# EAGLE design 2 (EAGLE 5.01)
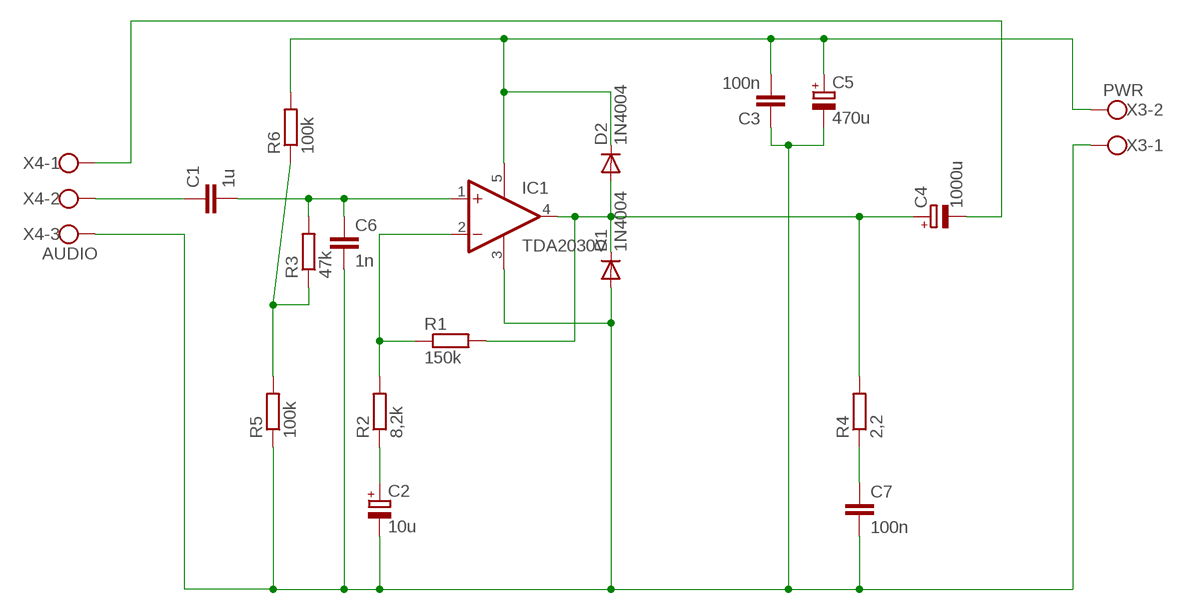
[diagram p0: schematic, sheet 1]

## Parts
C1  1u  C-EU075-042X103  [C075-042X103]
C2  10u  CPOL-EUE2.5-5  [E2,5-5]
C3  100n  C-EU075-032X103  [C075-032X103]
C4  1000u  CPOL-EUE5-10.5  [E5-10,5]
C5  470u  CPOL-EUE5-8.5  [E5-8,5]
C6  1n  C-EU050-025X075  [C050-025X075]
C7  100n  C-EU075-032X103  [C075-032X103]
D1  1N4004  [DO41-10]
D2  1N4004  [DO41-10]
IC1  TDA2030V  [CB360]
R1  150k  R-EU_0207/12  [0207/12]
R2  8,2k  R-EU_0207/12  [0207/12]
R3  47k  R-EU_0207/12  [0207/12]
R4  2,2  R-EU_0207/12  [0207/12]
R5  100k  R-EU_0207/12  [0207/12]
R6  100k  R-EU_0207/12  [0207/12]
X3  PWR  W237-102  [W237-102]
X4  AUDIO  W237-3E  [W237-3E]

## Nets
GND: C2.- C3.1 C5.- C6.2 C7.2 D1.A IC1.3(GND) R5.1 X3.1 X4.3
N$1: C4.- X4.1
N$2: R3.1 R5.2 R6.1
N$5: IC1.2(-IN) R1.1 R2.2
N$6: C2.+ R2.1
N$8: C4.+ D1.C D2.A IC1.4(OUT) R1.2 R4.2
N$9: C7.1 R4.1
N$11: C1.1 X4.2
SIGNAL: C1.2 C6.1 IC1.1(+IN) R3.2
VCC: C3.2 C5.+ D2.C IC1.5(V+) R6.2 X3.2

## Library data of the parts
C1 C3 C6 C7 = rcl:C-EU: CAPACITOR, European symbol
C2 C4 C5 = rcl:CPOL-EU: POLARIZED CAPACITOR, European symbol
D1 D2 = diode:1N4004: DIODE
IC1 = linear:TDA2030: Power OP AMP
R1-R6 = rcl:R-EU_: RESISTOR, European symbol
X3 = con-wago-500:W237-102: WAGO SCREW CLAMP
X4 = con-wago-508:W237-3E: WAGO SREW CLAMP

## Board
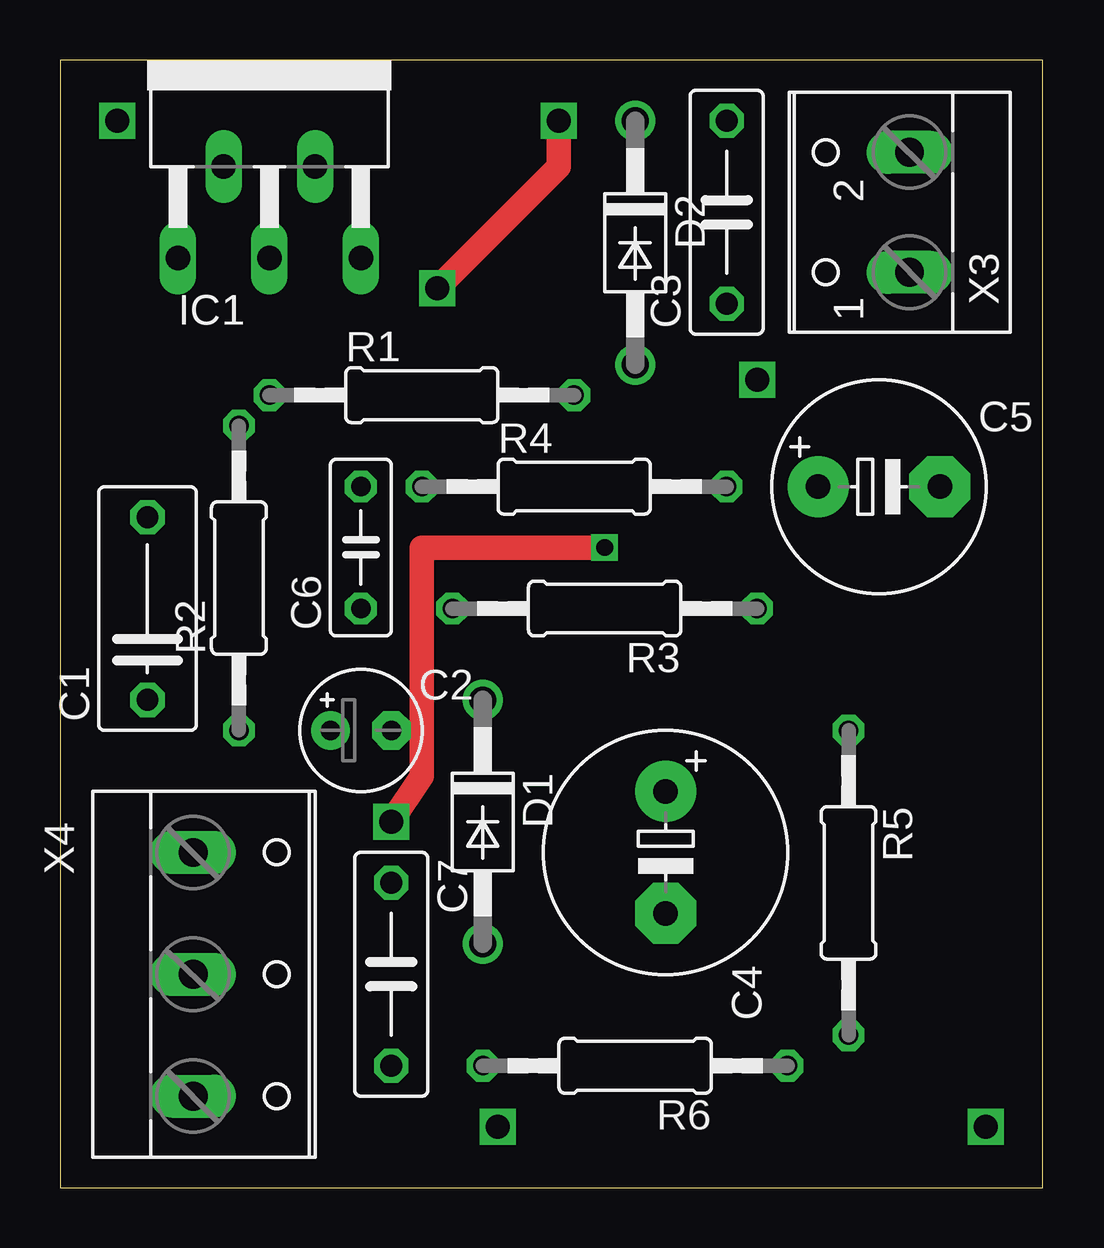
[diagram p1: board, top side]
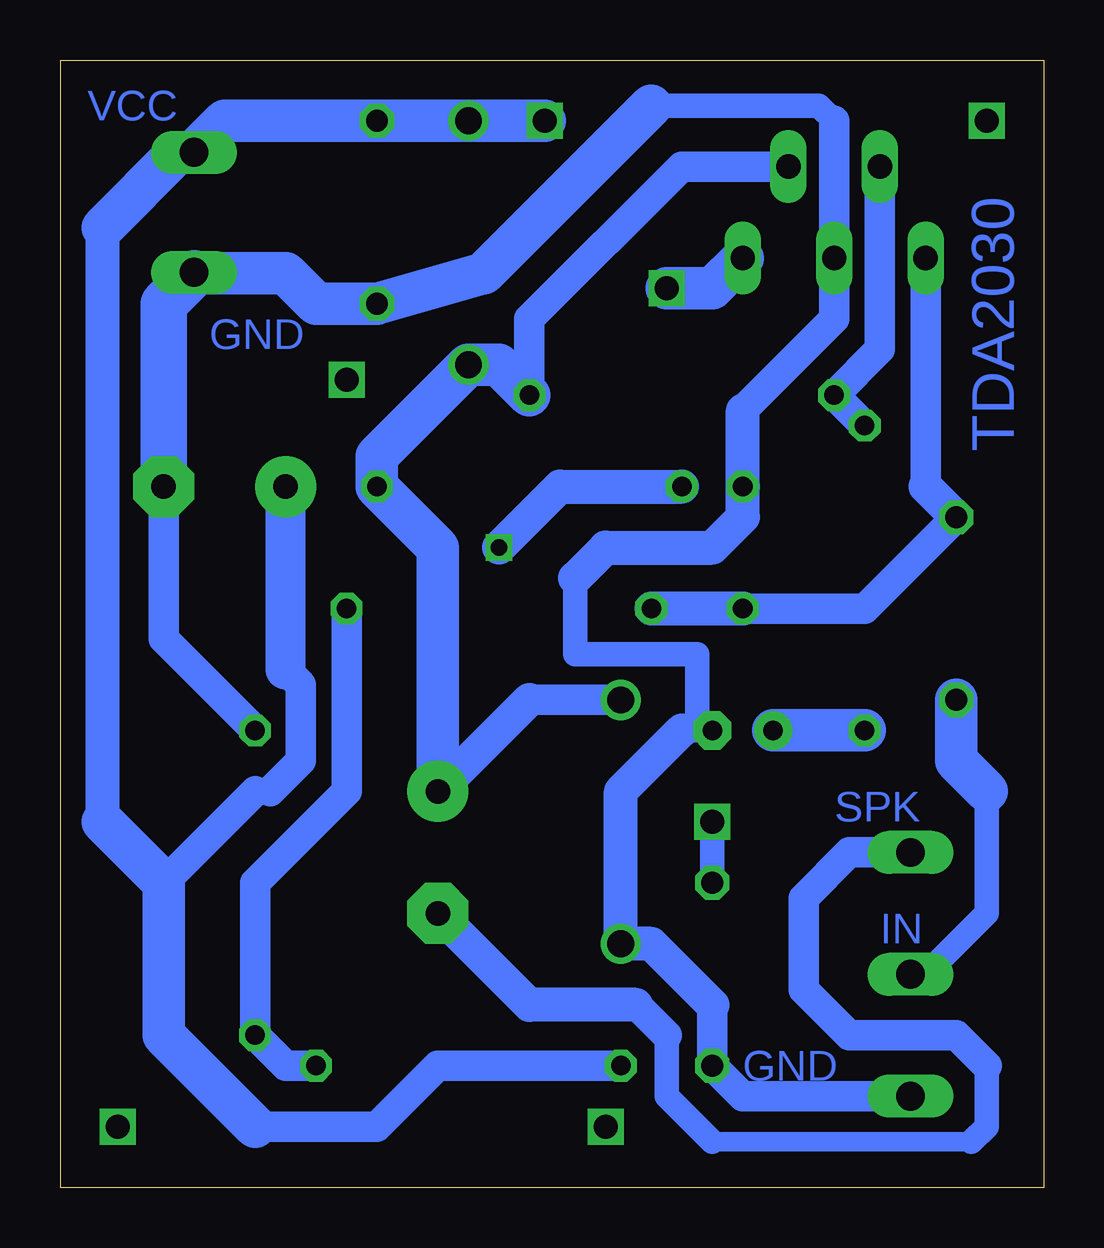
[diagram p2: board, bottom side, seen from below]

Size 40.94 x 46.98 mm. Coordinates in mm from the lower left corner, seen from the top.
Outline: 0,0 40.94,0 40.94,46.98 0,46.98 0,0
Copper layers (1*16): Top 0.035mm / dielectric 1.5mm / Bottom 0.035mm
Design rules "default": minimum track width 10mil, minimum drill 24mil, track to track 8mil, track to pad 8mil, pad to pad 8mil, via to via 8mil, smd to smd 8mil, copper to edge 40mil, drill to drill 8mil, minimum pad ring 10mil, minimum via ring 8mil, stop-mask expansion 4mil, vias tented up to drill 0mil, thermal gap 10mil

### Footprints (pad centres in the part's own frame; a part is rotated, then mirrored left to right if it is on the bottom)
C075-042X103 = drill 0.914 octagon: 1 -3.81,0; 2 3.81,0
E2,5-5 = drill 0.813 pad 1.6 round: + -1.27,0 | drill 0.813 pad 1.6 octagon: - 1.27,0
C075-032X103 = drill 0.914 octagon: 1 -3.81,0; 2 3.81,0
E5-10,5 = drill 1.016 pad 2.54 round: + -2.54,0 | drill 1.016 pad 2.54 octagon: - 2.54,0
E5-8,5 = drill 1.016 pad 2.54 round: + -2.54,0 | drill 1.016 pad 2.54 octagon: - 2.54,0
C050-025X075 = drill 0.813 octagon: 1 -2.54,0; 2 2.54,0
DO41-10 = drill 1.118 round: A 5.08,0; C -5.08,0
CB360 = drill 1.016 long: 1 -3.81,-8.255; 2 -1.905,-4.445; 3 0,-8.255; 4 1.905,-4.445; 5 3.81,-8.255
0207/12 = drill 0.813 octagon: 1 -6.35,0; 2 6.35,0
W237-102 = drill 1.194 long: 1 -2.5,-1.27; 2 2.5,-1.27
W237-3E = drill 1.194 long: 1 -5.08,-0.635; 2 0,-0.635; 3 5.08,-0.635

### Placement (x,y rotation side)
C1  3.64,24.13 90 top
C2  12.54,19.04 0 top
C3  27.78,40.63 90 top
C4  25.24,13.96 270 top
C5  34.12,29.21 0 top
C6  12.54,26.67 90 top
C7  13.8,8.89 270 top
D1  17.61,15.24 270 top
D2  23.96,39.36 270 top
IC1  8.72,46.98 0 top
R1  15.07,33.02 0 top
R2  7.46,25.39 90 top
R3  22.69,24.13 180 top
R4  21.43,29.21 0 top
R5  32.86,12.69 270 top
R6  23.96,5.07 180 top
X3  34.12,40.63 90 top
X4  6.18,8.89 270 top

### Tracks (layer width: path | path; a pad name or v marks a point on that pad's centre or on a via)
GND
  Bottom 1.016: 15.07,19.04 C2.- 14.44,19.68 14.44,22.22 19.52,22.22 19.52,25.39 | 8.72,44.44 9.36,45.08 16.35,45.08
  Bottom 1.27: R5.1 36.66,22.86 C5.- | 35.39,38.09 X3.1 | X4.3 12.54,3.81 C7.2 13.8,7.61 | 12.54,32.38 8.72,36.19 IC1.3 8.72,44.44
  Bottom 1.422: 13.8,7.61 16.35,10.15 D1.A 17.61,16.5 15.07,19.04 | 19.52,25.39 18.25,26.67 13.8,26.67 12.54,27.93 C6.2 12.54,32.38
  Bottom 1.778: 35.39,38.09 31.58,38.09 30.32,36.83 C3.1 23.33,38.09 16.35,45.08
  Bottom 1.93: C5.- 36.66,36.83 35.39,38.09
N$1
  Bottom 0.813: 3.01,1.9 13.8,1.9
  Bottom 1.016: 2.38,5.07 2.38,2.54 3.01,1.9 | 13.8,1.9 15.71,3.81 15.71,6.35
  Bottom 1.27: X4.1 8.09,13.96 10,12.06 10,8.25 8.09,6.35 3.64,6.35 2.38,5.07 | 15.71,6.35 16.98,7.61
  Bottom 1.422: 16.98,7.61 21.43,7.61 C4.-
N$2
  Bottom 1.27: R6.1 31.58,5.07 R5.2 32.86,12.69 29.04,16.5 R3.1
N$3  (via drill 1 pad 0.81)
  other vias: 2.38,44.44
N$4  (via drill 1)
  other vias: 38.57,2.54
N$5
  Bottom 1.27: R2.2 R1.1 6.82,34.92 IC1.2
N$6
  Bottom 1.778: R2.1 C2.+
N$7  (via drill 1)
  other vias: 29.04,33.65
N$8
  Bottom 1.27: D1.C 21.43,20.32 | R1.2 21.43,36.19 15.07,42.54 IC1.4
  Bottom 1.422: 21.43,20.32 C4.+
  Bottom 1.778: C4.+ 25.24,26.67 R4.2 27.78,30.47 D2.A 22.69,34.28 R1.2
N$9  (via drill 0.7, 1)
  Top 1.016: v13.8,15.24 15.07,17.14 15.07,26.67 v22.69,26.67
  Bottom 1.016: C7.1 v13.8,15.24
  Bottom 1.422: v22.69,26.67 20.15,29.21 R4.1
N$10  (via drill 1)
  other vias: 18.25,2.54
N$11
  Bottom 1.016: X4.2 4.92,8.89 2.38,11.43 2.38,16.5
  Bottom 1.778: 2.38,16.5 3.64,17.78 C1.1
SIGNAL
  Bottom 1.27: 4.92,29.21 IC1.1 | C1.2 7.46,24.13 C6.1
  Bottom 1.422: C1.2 4.92,29.21 | C6.1 R3.2
VCC  (via drill 1)
  Top 1.016: v15.71,37.46 20.79,42.54 v20.79,44.44
  Bottom 0.813: 32.86,16.5 32.22,16.5
  Bottom 1.016: X3.2 35.39,43.17
  Bottom 1.27: R6.2 25.24,5.07 27.78,2.54 32.86,2.54 | 36.66,12.69 32.86,16.5 | 32.22,16.5 30.95,17.78 30.95,20.95 31.58,21.58
  Bottom 1.422: 39.2,15.24 39.2,40
  Bottom 1.676: 31.58,21.58 C5.+
  Bottom 1.778: 32.86,2.54 36.66,6.35 36.66,12.69 39.2,15.24 | 35.39,43.17 34.12,44.44 C3.2 D2.C v20.79,44.44 | X3.2 36.07,43.13 39.2,40 | IC1.5 13.8,37.46 v15.71,37.46

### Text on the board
Bottom: VCC | TDA2030 | GND | SPK | IN | GND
